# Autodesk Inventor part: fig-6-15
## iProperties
Created: 2004-05
Part Number: fig-6-15
Document SubType Name: Modeling
Designer: CADCIM Technologies
Manufacturer: Standard
Standards Organization: Custom
Density: 1 g/cm^3
Author: CADCIM Technologies
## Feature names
1. Extrusion1
2. Extrusion2
3. Extrusion3
